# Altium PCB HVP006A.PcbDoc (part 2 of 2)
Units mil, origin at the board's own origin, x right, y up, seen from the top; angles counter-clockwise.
Board outline 1253 x 1919 mil, 4 copper layers (Top Layer, Signal Layer 1, Signal Layer 2, Bottom Layer), stack 61.2 mil thick; 55 components, 14 nets, 102 pads, 51 vias.
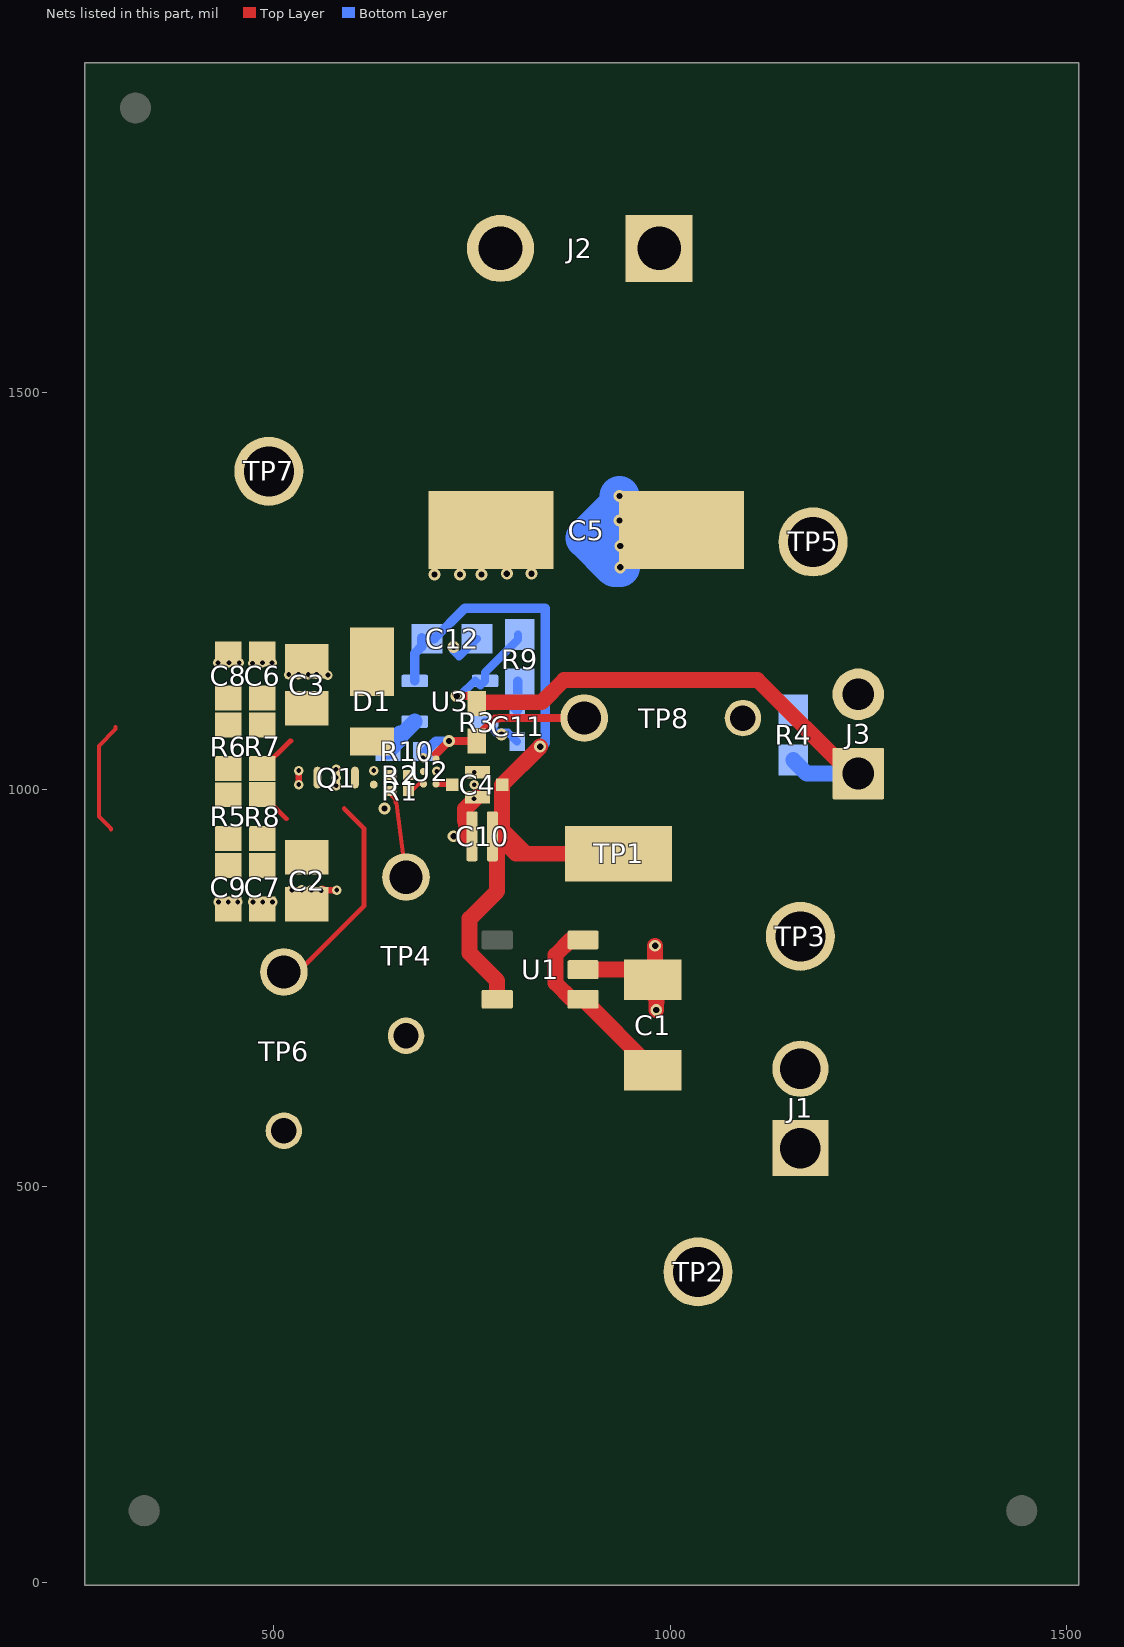
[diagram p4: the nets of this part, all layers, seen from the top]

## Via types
v1: diameter 15, hole 7.87, Top Layer to Bottom Layer, tented both sides, 18 vias
v2: diameter 12, hole 6, Top Layer to Signal Layer 1, tented both sides, 18 vias
v3: diameter 12, hole 6, Top Layer to Bottom Layer, tented both sides, 14 vias
v4: diameter 12, hole 6, Top Layer to Signal Layer 1, tented top, 1 vias

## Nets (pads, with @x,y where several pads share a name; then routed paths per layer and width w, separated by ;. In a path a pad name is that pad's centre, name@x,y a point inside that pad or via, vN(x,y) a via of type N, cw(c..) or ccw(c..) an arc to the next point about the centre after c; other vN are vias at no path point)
5V: C4.1 C10.1 C12.1 TP1.1 U1.5 U3.5 | length 982.2
  Top Layer w20: U1.5@781.87,735.6 781.87,758.87 747.18,793.55 747.18,837.21 781.87,871.9 781.87,939.37 783.5,941 ; C4.1@788,1006 v1(836,1054) ; C4.1@788.5,1006 787.75,1005.25 787.75,949.25 ; TP1.1@935,919 818,919 ; 783.5,941 805.5,919 818,919 ; 783.5,941 786.75,944.25 ; 786.75,944.25 786.75,950.25 787.75,949.25 ; 786.75,944.25 787.75,945.25 787.75,949.25 ; 787.75,949.25 818,919
  Bottom Layer w12: U3.5@677.96,1136.75 677.96,1171.46 686.5,1180 C12.1@686.5,1191 ; C12.1@693.5,1190 702.55,1190 740.75,1228.2 842.4,1228.2 842.4,1058.51 v1@835.73,1051.84
AN: C2.1 C3.1 C5.1 C6.1 C7.1 C8.1 C9.1 D1.1 J2.1 R5.2 R6.2 R7.2 R8.2 TP5.1 | length 314.8
  Top Layer w5: 295,949.39 295,950.8 279.8,966 279.8,1054.8 301,1076 301,1079
  Bottom Layer w50: 933,1317 893,1317 ; v1(936,1370) 936,1360 893,1317 ; v1(937,1280) 930,1280 893,1317
  other v1: 937,1307 936,1339
GATE: Q1.1 R1.2 R2.2 TP4.1 | length 114.1
  Top Layer w5: R1.2@647.98,1000 649.11,998.87 649.11,991.63 653.5,987.23 653.5,983.71 655,982.21 TP4.1@667,889.58
GND: C1.1 C4.3 C10.2 C11.2 C12.2 J1.2 J3.2 Q1.2 R4.1 TP3.1 TP4.2 TP6.2 TP8.2 U1.2 U2.B1 U2.C2 U3.3 | length 331.8
  Top Layer w20: 742.5,941 742.5,959.5 741,961 741,975.25 C4.3@756,990.25 ; U1.2@890.13,773 965.09,773 C1.1@978,760.09 ; v1(981,803) 981,763.09 C1.1@978,760.09 ; v1(982.4,722) 982.4,731.4 983,732 983,737 978,742 C1.1@978,760.09
  Bottom Layer w10: v1(727,1179.8) 727,1174.5 734,1167.5 C12.2@756.5,1190 ; U3.3@766.55,1085.56 780.07,1072.04 791.01,1072.04 795.28,1072.04 C11.2@807,1060.31
  other v1: 727,941 640,976 787.4,1069.4
  other v2: 752.6,988.4 753,1006 753,1021.8 705.8,1023 626.24,1023.86 688.4,1039.8
KA: D1.2 Q1.3 Q1.5 R5.1 R6.1 R7.1 R8.1 TP6.1 | length 362
  Top Layer w6: R8.1@486,993.42 516.21,963.21 ; R7.1@486,1026.25 520.75,1061 522.19,1061 ; TP6.1@513,770 531,770 614,853 614,951 589,976
NetC1_2: C1.2 J1.1 TP2.1 U1.1 U1.3 | length 247.1
  Top Layer w20: U1.3@890.13,810.4 874.4,810.4 855.45,791.45 855.45,756.15 876,735.6 U1.1@890.13,735.6 978,647.73 C1.2@978,645.91
NetC4_2: C4.2 U2.A1 | length 24.4
  Top Layer w8: C4.2@724.5,1007 723.5,1007 U2.A1@708,1007 ; U2.A1@708,1007 U2.A1@704.75,1007 U2.A1@708,1007
  Top Layer w12: C4.2@723.5,1007 C4.2@724.5,1006
NetC11_1: C11.1 R9.2 U3.2 | length 82.4
  Bottom Layer w12: U3.2@766.55,1111.16 795.53,1111.16 C11.1@807,1099.68 808,1100.68 808,1132.5 R9.2@808,1136.44
NetJ3_1: J3.1 R3.2 R4.2 R9.1 U3.1 | length 816.8
  Top Layer w10: v1(730.8,1117.8) R3.2@746.82,1117.8 ; R3.2@757.38,1110 R3.2@756,1111.38 ; R3.2@746.82,1117.8 R3.2@756,1108.62 R3.2@756,1111.38 ; R3.2@746.82,1117.8 754.79,1117.8 756,1116.59 R3.2@756,1111.38
  Top Layer w12: R3.2@756,1108.62 757.38,1110 R3.2@759,1111.62
  Top Layer w20: R3.2@757.38,1110 838,1110 866,1138 1110,1138 1228,1020 J3.1@1237,1020 J3.1@1230,1027
  Bottom Layer w10: v1(730.8,1117.8) 734.48,1117.8 754.08,1137.4 760.64,1130.84 U3.1@766.55,1136.75 766.55,1147.52 808,1188.98 R9.1@808,1195.5
  Bottom Layer w20: R4.2@1155,1037.01 1172.01,1020 J3.1@1237,1020
NetR1_1: R1.1 U2.A2 | length 21.9
  Top Layer w5: R1.1@670.02,1000 676.02,1000 683.02,1007 684.98,1007 U2.A2@689,1007
NetR2_1: R2.1 U2.B2
NetR3_1: R3.1 R10.2 TP8.1 U2.C1 | length 248.2
  Top Layer w8: U2.C1@704.75,1038.5 704.75,1044.75
  Top Layer w10: 704.75,1044.75 v1(721,1061) 755.62,1061 R3.1@756,1061.38 756,1066.8 778.74,1089.54 784.16,1089.54 784.62,1090 TP8.1@890,1090
  Bottom Layer w12: R10.2@691.62,1048 704.62,1061 v1(721,1061)
NetR10_1: R10.1 U3.4 | length 53.5
  Bottom Layer w20: R10.1@644.38,1048 659.36,1062.98 659.36,1070.39 662.79,1070.39 U3.4@677.96,1085.56
PGND: C2.2 C3.2 C5.2 C6.2 C7.2 C8.2 C9.2 J2.2 Q1.4 Q1.6 Q1.7 TP7.1 | length 140.8
  Top Layer w8: C8.2@430.2,1157.82 C8.2@443,1170.61 443,1164 C8.2@444,1163 ; C6.2@474.2,1158.82 C6.2@486,1170.61 C6.2@486,1162.2 ; v2(531.76,1006.14) v2(531.76,1023.86) ; C3.2@541.8,1163.93 C3.2@559.53,1146.2 ; C2.2@542,855.47 561.73,875.2 563.73,873.2 v3(579.8,873.2)
  other v1: 703,1271 735,1271 762,1271 794,1272 825,1272
  other v2: 560,872.4 523.2,873.4 535.6,873.4 547.8,873.4 579,1015 578.8,1025.4 519.2,1144.8 531.4,1144.8 543.6,1144.8 554,1145
  other v3: 430.6,858.2 442.8,858.2 455,858.2 474,858.2 486.4,858.2 498.8,858.2 568.6,1144.2 473.6,1159 430,1159.8 443.8,1159.8 456.8,1159.8 486,1159.8 498.2,1159.8
  other v4: 579,1004.8
pads on no net: FID1.1 FID2.1 FID3.1 H1.0 H2.0 H3.0 H4.0 Q1. U1.4

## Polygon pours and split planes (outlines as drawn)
AN on Top Layer "TOP_LAYER_AN_P036" (solid, remove dead copper, pour order 36): 870,1760 870,1226 1106,1226 1288,1408 1288,1793 1273,1808 1272,1807 891,1807 870,1786
PGND on Top Layer "TOP_LAYER_PGND_P034" (solid, remove dead copper, pour order 34): 303.43,1812.48 299.43,1143 480.3,1143 576.63,1146.51 589,1216 855,1260.62 855,1797 841,1811
AN on Top Layer "TOP_LAYER_AN_P026" (solid, remove dead copper, pour order 26): 295,889 558.12,889 577,907.88 577,955 565,967 434,967 295,967
AN on Top Layer "TOP_LAYER_AN_P010" (solid, remove dead copper, pour order 10): 294,1060.99 516,1066 652,1093 1105,1237 870.31,1263 592,1204 294,1135
KA on Top Layer "TOP_LAYER_KA_P007" (solid, pour order 7): 610.67,1072 296,1047 296,972.63 614,949
5V on Top Layer "TOP_LAYER_5V_P062" (solid, pour order 62): 729,708 844,708 844,1053 841,1050 786,1050 739,1003 729,898
GATE on Top Layer "TOP_LAYER_GATE_P060" (solid, pour order 60): 620,1011 635,1026 641,1026 657,1026 657,992 626,994
NetR1_1 on Top Layer "TOP_LAYER_NETR1_1_P006" (solid, pour order 6): 663,1005 663,993 687,993 694,1000 694,1003 694,1013 669,1013 663,1007
NetR2_1 on Top Layer "TOP_LAYER_NETR2_1_P056" (solid, pour order 56): 661,1028 661,1011 672,1011 678,1017 688,1017 695,1017 696,1018 696,1028
PGND on Top Layer "TOP_LAYER_PGND_P016" (solid, remove dead copper, pour order 16): 416.44,940.13 417.44,939.13 417.44,874 291,874 291,72 688,72 688,759.57 554.44,893.13 547.44,893.13 457.44,890.13 449.44,910.13
NetC1_2 on Top Layer "TOP_LAYER_NETC1_2_P038" (solid, remove dead copper, pour order 38): 709,665 710,664 710,58 1276,58 1276,342 1276,597 1272,601 1080,601 1000,681 996,681 924,834.02 851.75,834.02 837,736
GND on Top Layer "TOP_LAYER_GND_P040" (solid, remove dead copper, pour order 40): 941,808 939,806 939,723 1052,610 1250,610 1267,627 1267,647 1269,649 1269,850 1223,896 1151,896 1088,896 1019,827
PGND on Signal Layer 1 "SIGNAL_LAYER_1_PGND_P008" (solid, remove dead copper, pour order 8): 319,72 1280,72 1280,1889.01 319,1889
GND on Signal Layer 1 "SIGNAL_LAYER_1_GND_P005" (solid, remove dead copper, pour order 5): 620,1035 620,1003.51 667,940 667,852 476,852 476,53 1287.31,53 1287.31,1228 659,1228 659,1035
GND on Signal Layer 2 "SIGNAL_LAYER_2_GND_P046" (solid, remove dead copper, pour order 46): 620,1034 620,1003.51 667,940 667,852 476,852 476,53 1287.31,53 1287.31,1228 665.37,1228 665.37,1034
PGND on Signal Layer 2 "SIGNAL_LAYER_2_PGND_P048" (solid, pour order 48): 305,80 1273.51,80 1283.5,1868 305,1868
PGND on Bottom Layer "BOTTOM_LAYER_PGND_P052" (solid, pour order 52): 307,741 307,68 462,68 1277.39,1095 1277.39,1862 307,1862
GND on Bottom Layer "BOTTOM_LAYER_GND_P004" (solid, remove dead copper, pour order 4): 628,992.7 667,940 667,852 476,852 476,53 1287.31,53 1287.31,1233 628,1233

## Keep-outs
Keep-Out Layer:
  text ".Layer_Name" at 577,-858.49 h60

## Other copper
Top Layer:
  rectangle net GND: 628,964 646,984.13
  rectangle net KA: 576.4,965.87 598,986
  text ".Layer_Name" at 577,-858.49 h60
Bottom Layer:
  text ".Layer_Name" at 577,-858.49 h60

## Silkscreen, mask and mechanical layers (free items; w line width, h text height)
Top Overlay:
  lines w3.94: 570.52,1088.71 571.76,1087.47 571.76,1043.24 571.76,1040.81 578.58,1034 657,1034 669,1046 669,1061 ; 571.88,977 792,977 803,988 803,988.99 803,1052 794,1061 669,1061 ; 667,1059 669,1061
  lines w10: 357,1330 357,1248 419,1186 ; 418,834 419,835 ; 420,1185 419,1186 ; 569,1090.73 569,1185 419,1186 ; 570.88,978 570,835 568,833 567,833 565,835 419,835 ; 419,835 419,1186
  text "Driver and Load / Area: 42sqmm" at 474,1326 h72.83 r90
  text ".Layer_Name" at 577,-858.49 h60
Bottom Overlay:
  text ".Layer_Name" at 577,-858.49 h60
Top Paste:
  text ".Layer_Name" at 577,-858.49 h60
Bottom Paste:
  text ".Layer_Name" at 577,-858.49 h60
Top Solder:
  circle w10: c587,976 r4.24
  circle w10: c638,974 r3.61
  rectangle: 300,895 417,953
  rectangle: 301,981 418,1039
  rectangle: 302,1067 419,1125
  text ".Layer_Name" at 577,-858.49 h60
  text ".Layer_Name" at 577,-858.49 h60
Bottom Solder:
  text ".Layer_Name" at 577,-858.49 h60
Drill Guide:
  text ".Layer_Name" at 577,-858.49 h60
M1 Board Outline:
  lines w10: 258,-2 258,1911 263,1916 1516,1916 1517,1915 1517,3 1512,-2 258,-2
  text ".Layer_Name" at 577,-858.49 h60
M2 Board Dimensions:
  text ".Layer_Name" at 577,-858.49 h60
M3 3D STEP Top:
  text ".Layer_Name" at 577,-858.49 h60
M4 3D STEP Bottom:
  text ".Layer_Name" at 577,-858.49 h60
M5 Assembly Top:
  lines w10: -292,-930.17 6308,-930.17 ; -292,-726.83 6310,-726.83 ; -292,-523.5 -292,-1133.5 3713,-1133.5 6310,-1133.5 6310,-523.5 -291.5,-523.5 -291.5,-1133.5 1284,-1133.5 ; 2173,-1133.5 2173,-523.5 ; 3440,-726.83 3440,-523.5 ; 4280,-726.83 4280,-523.5 ; 4902,-1140 4902,-937.17
  text "COMPONENTS MARKED 'DNP' SHOULD NOT BE POPULATED." at 1153.5,-318.5 h60
  text "ASSEMBLY VARIANT:" at 1153,-434 h60
  text ".VariantName" at 2189,-434 h60
  text "PCB VIEWED FROM TOP SIDE" at -228.5,-655.67 h60
  text "BOARD #:" at 2248,-655.67 h60
  text ".PRJ_Number" at 2793.5,-655.67 h60
  text "REV:" at 3638,-655.67 h60
  text ".PCB_Rev" at 3929.5,-655.67 h60
  text "SVN REV:" at 4476,-655.67 h60
  text ".VersionControl_RevNumber" at 4982,-655.67 h60
  text "TID #:" at 2248,-859 h60
  text ".TID" at 2793.5,-859 h60
  text "PLOT NAME =" at -228.5,-1064.34 h60
  text ".plot_File_Name" at 577,-1064.34 h60
  text "GENERATED    :" at 2250,-1064.34 h60
  text ".Print_Date" at 3119.5,-1064.34 h60
  text ".Print_Time" at 3848.5,-1064.34 h60
  text "TEXAS INSTRUMENTS" at 5113,-1064.34 h60
M6 Assembly Bottom:
  lines w10: -292.5,-727.33 6309.5,-727.33 ; -290.5,-930.67 6309.5,-930.67 ; 1115.5,-1140.5 1115.5,-937.67 ; 1737.5,-727.33 1737.5,-524 ; 2577.5,-727.33 2577.5,-524 ; 3844.5,-1134 3844.5,-524 ; 4733.5,-1134 6309,-1134 6309,-524 -292.5,-524 -292.5,-1134 2304.5,-1134 6309.5,-1134 6309.5,-524
  text "COMPONENTS MARKED 'DNP' SHOULD NOT BE POPULATED." at 6102,-318 h60
  text ".VariantName" at 5058,-434 h60
  text "ASSEMBLY VARIANT:" at 6097,-434 h60
  text ".VersionControl_RevNumber" at 1035.5,-656.17 h60
  text "SVN REV:" at 1541.5,-656.17 h60
  text ".PCB_Rev" at 2088,-656.17 h60
  text "REV:" at 2379.5,-656.17 h60
  text ".PRJ_Number" at 3224,-656.17 h60
  text "BOARD #:" at 3769.5,-656.17 h60
  text "PCB VIEWED FROM BOTTOM SIDE" at 6246,-656.17 h60
  text ".TID" at 3224,-859.5 h60
  text "TID #:" at 3769.5,-859.5 h60
  text "TEXAS INSTRUMENTS" at 904.5,-1064.84 h60
  text ".Print_Time" at 2169,-1064.84 h60
  text ".Print_Date" at 2898,-1064.84 h60
  text "GENERATED    :" at 3767.5,-1064.84 h60
  text ".plot_File_Name" at 5440.5,-1064.84 h60
  text "PLOT NAME =" at 6246,-1064.84 h60
M9 Title Sheet:
  drawing of 57 lines, arcs and shapes, not listed
  text "1" at 739.84,8036.5 h70
  text "2" at 3235.5,8036.5 h70
  text "3" at 5724.84,8036.5 h70
  text "4" at 8231.51,8036.5 h70
  text "5" at 10730.5,8036.5 h70
  text "6" at 13235.5,8036.5 h70
  text "A" at -416.5,6893.5 h70
  text "A" at 14383.5,6893.5 h70
  text "B" at -416.5,4513.5 h70
  text "B" at 14383.5,4513.5 h70
  text "C" at -416.5,2138.5 h70
  text "C" at 14383.5,2138.5 h70
  text "PROJECT TITLE:" at 11343.5,277.5 h45
  text ".PRJ_Title" at 11393.5,144.17 h70
  text "DESIGNED FOR:" at 11343.5,-23.5 h45
  text ".PRJ_Customer" at 11393.5,-163.5 h70
  text "D" at -416.5,-231.5 h70
  text "D" at 14383.5,-231.5 h70
  text "FILE NAME:" at 11343.5,-323.5 h45
  text ".PCB_File_Name_No_Path" at 11393.5,-443.5 h70
  text "Texas Instruments (TI) and/or its licensors do not warrant the accuracy or completeness of this specification" at 6374,-605.34 h45
  text "ENGINEER:" at 11343.5,-613.5 h45
  text "LAYOUT BY:" at 12848.5,-613.5 h45
  text "or any information contained therein. TI and/or its licensors do not warrant that this design will meet" at 6329.01,-718 h45
  text ".PRJ_Engineer" at 11393.5,-768.49 h70
  text ".PCB_Layout" at 12899,-768.49 h70
  text "the specifications, will be suitable for your application or fit for any particular purpose, or will operate in" at 6329.01,-830.67 h45
  text ".Layer_Name" at 577,-858.49 h60
  text "ALTIUM DESIGNER VERSION:" at 12848.5,-923.5 h45
  text "an implementation. TI and/or its licensors do not warrant that the design is production worthy. You should" at 6329.01,-943.33 h45
  text "completely validate and test your design implementation to confirm the system functionality for your application." at 6374,-1056 h45
  text ".print_Scale" at 11393.5,-1056.83 h70
  text ".Application_BuildNumber" at 12899,-1056.83 h70
  text "1" at 739.84,-1263.5 h70
  text "2" at 3235.5,-1263.5 h70
  text "3" at 5724.84,-1263.5 h70
  text "4" at 8231.51,-1263.5 h70
  text "5" at 10730.5,-1263.5 h70
  text "6" at 13235.5,-1263.5 h70
M10 Fab Notes:
  drawing of 173 lines, arcs and shapes, not listed
  text "DESIGN INFORMATION" at 12378.02,6201 h60
  text "MIN. TRACK WIDTH:" at 11733.46,6021 h60
  text "5" at 12829.7,6021 h60
  text "MIL" at 12984.46,6021 h60
  text "MIN. CLEARANCE:" at 11733.46,5889 h60
  text "0.2" at 12769.7,5889 h60
  text "mm" at 12984.46,5889 h60
  text "MIN. VIA PAD SIZE:" at 11733.46,5757 h60
  text "10" at 12799.71,5757 h60
  text "MIL" at 12984.46,5757 h60
  text "0.05mm (2MIL)" at 12428.46,5615.29 h60
  text "MINIMUM ANNULAR RING" at 11404.23,5611 h60
  text "EXTERNAL" at 13136.46,5611 h60
  text "PER" at 11604.23,5493 h60
  text "IPC-D-275 CLASS 2 LEVEL C" at 11824.23,5493 h60
  text "MIL, HOLES" at 13312.46,5380.71 h60
  text "+/-" at 12920,5380 h60
  text "+/-" at 13774,5380 h60
  text "REGISTRATION TOLERANCES:" at 11404.23,5375 h60
  text "METAL" at 12604,5375 h60
  text "5" at 13180.2,5375 h60
  text "3" at 14013.2,5375 h60
  text "MIL" at 14129.46,5375 h60
  text "+/-" at 13774,5262 h60
  text "HOLE SIZE TOLERANCE (UNLESS OTHERWISE SPECIFIED):" at 11404.23,5257 h60
  text "3" at 14013.2,5257 h60
  text "MIL" at 14129.46,5257 h60
  text "NOTE:  Fill all 6 mil vias and plate shut then polish flat." at 11393.8,5097 h90
  text "MATERIAL:" at 11329.46,5047.54 h60
  text "FR-4 High Tg" at 12315.9,4907.21 h60
  text "FR-408" at 11750.46,4898.64 h60
  text "OTHER" at 13238.46,4898.64 h60
  text "X" at 12161,4895 h60
  text "62 MIL (1.6mm) +/-10%" at 12070.56,4735.92 h60
  text "THICKNESS:" at 11404.23,4731.64 h60
  text "X" at 11942.4,4731.64 h60
  text "OTHER" at 13355.46,4731.64 h60
  text "TOLERANCE:" at 11404.23,4573.64 h60
  text "X" at 12243.53,4573.64 h60
  text "ANSI IPC-6012 TYPE 3 CLASS 2" at 12430.48,4573.64 h60
  text "OTHER +/-" at 12430.46,4417.64 h60
  text "BOW & TWIST:" at 11404.23,4260.64 h60
  text "X" at 12243.53,4260.64 h60
  text "ANSI IPC-6012 TYPE 3 CLASS 2" at 12430.48,4260.64 h60
  text "OTHER +/-" at 12430.46,4102.13 h60
  text "DRILLING:" at 11329.46,3963.64 h60
  text "REFERENCE:" at 11404.23,3846.64 h60
  text "X" at 12052.46,3846.64 h60
  text "AS SHOWN" at 12239.46,3846.64 h60
  text "X" at 12953.46,3846.64 h60
  text "NC_DRILL FILES" at 13090.46,3846.64 h60
  text "PTH COPPER THICKNESS:" at 11404.23,3688.64 h60
  text "X" at 12534.46,3688.64 h60
  text "20-30 um" at 12671.46,3688.64 h60
  text "OTHER" at 13388.46,3688.64 h60
  text "BOARD FINISH:" at 11329.46,3529.64 h60
  text "SILKSCREEN:" at 11484.68,3411.64 h60
  text "X" at 12433.46,3411.64 h60
  text "TOP" at 12559.46,3411.64 h60
  text "X" at 12943.46,3411.64 h60
  text "BOTTOM" at 13070.46,3411.64 h60
  text "FAB NOTE:  Fill all 6 mil vias and plate shut then polish flat." at 26.4,3323.6 h90
  text "SILKSCREEN COLOR:" at 11484.68,3244.64 h60
  text "X" at 12432.42,3244.64 h60
  text "WHITE" at 12559.46,3244.64 h60
  text "OTHER" at 13070.46,3244.64 h60
  text "X" at 12563.42,3085.44 h60
  text "GREEN" at 12690.46,3085.44 h60
  text "OTHER" at 13308.46,3085.44 h60
  text "SOLDER RESIST COLOR:" at 11484.68,3074.64 h60
  text "X" at 12563.42,2915.44 h60
  text "MATTE" at 12690.46,2915.44 h60
  text "SEMI-GLOSS" at 13308,2914.8 h60
  text "IMMERSION GOLD (ENIG)" at 12390.46,2726.92 h60
  text "ENEPIG" at 13728,2723.64 h60
  text "SURFACE FINISH:" at 11329.46,2722.64 h60
  text "X" at 12203.51,2722.64 h60
  text "IMM. TIN/SILVER OR EQUIV" at 11659,2565.64 h60
  text "OTHER" at 13090.46,2565.64 h60
  text "ARRAY/PANEL:" at 11329.46,2386.64 h60
  text "CUT AND TRIM PER M1 BOARD OUTLINE" at 12390.46,2382.35 h60
  text "N.C. ROUTE" at 12390.46,2230.64 h60
  text "X" at 13069.46,2230.64 h60
  text "V. SCORE" at 13256.46,2230.64 h60
  text "CERTIFICATION:" at 11329.46,2093.64 h60
  text "MATERIALS AND WORKMANSHIP FOR ALL PCBS" at 12054.46,2093.64 h60
  text "TO MEET OR EXCEED THE REQUIREMENTS OF:" at 12054.46,1995.64 h60
  text "X" at 11680.96,1859.13 h60
  text "ANSI IPC-A-600F CLASS ->" at 11819.96,1859.13 h60
  text "X" at 13459.02,1859.13 h60
  text "2" at 13577.96,1859.14 h60
  text "1" at 13262.96,1857.64 h60
  text "3" at 13931.96,1857.64 h60
  text "X" at 12495.02,1699.64 h60
  text "RoHS" at 12631.96,1699.64 h60
  text "OTHER" at 13276.36,1699.64 h60
  text "PER ORDER" at 13673.42,1699.64 h60
  text "ALL BOARDS MUST MEET OR EXCEED UL94-V0 REQUIREMENTS." at 11357,1534 h60
  text "PCB MUST BEAR THE UL94V-0 UL REGISTERED MATERIAL ID NUMBER" at 11357,1414 h60
  text "ADDITIONAL REQUIREMENTS:" at 11329.46,1240.64 h60
  text "MICROSECTION:" at 11404.23,1125.64 h60
  text "YES" at 12309.96,1125.64 h60
  text "REQUIRED" at 13171.46,969.49 h60
  text "BARE BOARD ELEC. TEST:" at 11404.23,966.64 h60
  text "NONE" at 12709.96,966.64 h60
  text "X" at 13044.46,966.64 h60
  text "PER ORDER" at 13763.46,966.64 h60
  text ".Layer_Name" at 577,-858.49 h60
M11 Gerber Information:
  lines w10: -292,-930.17 6308,-930.17 ; -292,-726.83 6310,-726.83 ; -292,-523.5 -292,-1133.5 3713,-1133.5 6310,-1133.5 6310,-523.5 -291.5,-523.5 -291.5,-1133.5 1284,-1133.5 ; 2173,-1133.5 2173,-523.5 ; 3440,-726.83 3440,-523.5 ; 4280,-726.83 4280,-523.5 ; 4902,-1140 4902,-937.17
  text "ALL ARTWORK VIEWED FROM TOP SIDE" at -228.5,-655.67 h60
  text "BOARD #:" at 2248,-655.67 h60
  text ".PRJ_Number" at 2793.5,-655.67 h60
  text "REV:" at 3638,-655.67 h60
  text ".PCB_Rev" at 3929.5,-655.67 h60
  text "SVN REV:" at 4476,-655.67 h60
  text ".VersionControl_RevNumber" at 4982,-655.67 h60
  text "LAYER NAME =" at -228.5,-858.49 h60
  text "TID #:" at 2248,-859 h60
  text ".TID" at 2793.5,-859 h60
  text "PLOT NAME =" at -228.5,-1064.34 h60
  text ".plot_File_Name" at 577,-1064.34 h60
  text "GENERATED    :" at 2250,-1064.34 h60
  text ".Print_Date" at 3119.5,-1064.34 h60
  text ".Print_Time" at 3848.5,-1064.34 h60
  text "TEXAS INSTRUMENTS" at 5113,-1064.34 h60
M12 Stackup:
  drawing of 295 lines, arcs and shapes, not listed
  text "Layer" at 9728.74,7834 h60
  text "Name" at 10138.66,7834 h60
  text "Material" at 11078.4,7834 h60
  text "Thickness" at 11938.16,7834 h60
  text "Constant" at 12588,7834 h60
  text "Board Layer Stack" at 13157.86,7834 h60
  text "1" at 9728.74,7714 h60
  text "Top Overlay" at 10138.66,7714 h60
  text "2" at 9728.74,7594 h60
  text "Top Solder" at 10138.66,7594 h60
  text "Solder Resist" at 11078.4,7594 h60
  text "0.40mil" at 11938.16,7594 h60
  text "3.5" at 12588,7594 h60
  text "3" at 9728.74,7474 h60
  text "Top Layer" at 10138.66,7474 h60
  text "Copper" at 11078.4,7474 h60
  text "1.40mil" at 11938.16,7474 h60
  text "4" at 9728.74,7354 h60
  text "Dielectric1" at 10138.66,7354 h60
  text "FR-4" at 11078.4,7354 h60
  text "5.00mil" at 11938.16,7354 h60
  text "4.2" at 12588,7354 h60
  text "5" at 9728.74,7234 h60
  text "Signal Layer 1" at 10138.66,7234 h60
  text "Copper" at 11078.4,7234 h60
  text "1.42mil" at 11938.16,7234 h60
  text "6" at 9728.74,7114 h60
  text "Dielectric 3" at 10138.66,7114 h60
  text "45.57mil" at 11938.16,7114 h60
  text "4.2" at 12588,7114 h60
  text "7" at 9728.74,6994 h60
  text "Signal Layer 2" at 10138.66,6994 h60
  text "Copper" at 11078.4,6994 h60
  text "1.42mil" at 11938.16,6994 h60
  text "8" at 9728.74,6874 h60
  text "Dielectric 2" at 10138.66,6874 h60
  text "5.00mil" at 11938.16,6874 h60
  text "4.2" at 12588,6874 h60
  text "9" at 9728.74,6754 h60
  text "Bottom Layer" at 10138.66,6754 h60
  text "Copper" at 11078.4,6754 h60
  text "1.40mil" at 11938.16,6754 h60
  text "10" at 9728.74,6634 h60
  text "Bottom Solder" at 10138.66,6634 h60
  text "Solder Resist" at 11078.4,6634 h60
  text "0.40mil" at 11938.16,6634 h60
  text "3.5" at 12588,6634 h60
  text "11" at 9728.74,6514 h60
  text "Bottom Overlay" at 10138.66,6514 h60
  text ".Layer_Name" at 577,-858.49 h60
M13 Component Bodies Top:
  text ".Layer_Name" at 577,-858.49 h60
M14 Component Bodies Bottom:
  text ".Layer_Name" at 577,-858.49 h60
M15 Courtyards Top:
  text ".Layer_Name" at 577,-858.49 h60
M16 Courtyards Bottom:
  text ".Layer_Name" at 577,-858.49 h60
Drill Drawing:
  circle w10: c5936.73,2870.26 r27.63
  lines w10: 5909.1,2345.28 5964.36,2345.28 5964.36,2400.54 5909.1,2400.54 5909.1,2345.28 ; 5909.1,2524.88 5964.36,2524.88 5936.73,2469.62 5909.1,2524.88 ; 5909.1,2607.77 5922.91,2607.77 5936.73,2593.95 5950.54,2607.77 5964.36,2607.77 5950.54,2621.58 5964.36,2635.4 5950.54,2635.4 5936.73,2649.22 5922.91,2635.4 5909.1,2635.4 5922.91,2621.58 5909.1,2607.77 ; 5909.1,2718.29 5936.73,2732.1 5964.36,2718.29 5950.54,2745.92 5964.36,2773.55 5936.73,2759.73 5909.1,2773.55 5922.91,2745.92 5909.1,2718.29 ; 5909.1,2966.96 5964.36,2966.96 5964.36,3022.22 5909.1,3022.22 5909.1,2966.96 ; 5909.1,3091.3 5909.1,3105.11 5922.91,3118.93 5909.1,3132.74 5909.1,3146.56 5922.91,3146.56 5936.73,3132.74 5950.54,3146.56 5964.36,3146.56 5964.36,3132.74 5950.54,3118.93 5964.36,3105.11 5964.36,3091.3 5950.54,3091.3 5936.73,3105.11 5922.91,3091.3 5909.1,3091.3 ; 5909.1,3243.26 5936.73,3215.63 5964.36,3243.26 5936.73,3270.89 5909.1,3243.26 ; 5920.15,2978.01 5953.3,2978.01 5953.3,3011.17 5920.15,3011.17 5920.15,2978.01
  lines w12: 5806.2,1755.33 9044.82,1755.33 ; 5806.2,1879.66 9044.82,1879.66 ; 5859,2307.98 8934.93,2307.98 ; 5859,3302.66 8934.93,3302.66 ; 6143.95,1630.99 6143.95,2004 ; 6196.75,2183.65 6196.75,3427 ; 6475.76,1630.99 6475.76,2004 ; 6528.56,2183.65 6528.56,3427 ; 7111.86,1630.99 7111.86,2004 ; 7164.66,2183.65 7164.66,3427 ; 7370.86,1630.99 7370.86,2004 ; 7423.66,2183.65 7423.66,3427 ; 7745.84,1630.99 7745.84,2004 ; 7798.64,2183.65 7798.64,3427 ; 8478.63,1630.99 8478.63,2004 ; 8522.86,2183.65 8522.86,3427 ; 5806.2,1630.99 9044.82,1630.99 9044.82,2004 5806.2,2004 5806.2,1630.99 ; 5859,2183.65 8934.93,2183.65 8934.93,3427 5859,3427 5859,2183.65
  text "Symbol" at 5933.6,3339.97 h72
  text "Quantity" at 6234.05,3339.97 h72
  text "Finished Hole Size" at 6565.86,3339.97 h72
  text "Plated" at 7201.96,3339.97 h72
  text "Hole Type" at 7460.96,3339.97 h72
  text "Drill Layer Pair" at 7835.94,3339.97 h72
  text "Tolerance" at 8560.16,3339.97 h72
  text "14" at 6234.05,3215.63 h60
  text "6.00mil (0.152mm)" at 6565.86,3215.63 h60
  text "PTH" at 7201.96,3215.63 h60
  text "Round" at 7460.96,3215.63 h60
  text "Top Layer - Bottom Layer" at 7835.94,3215.63 h60
  text "18" at 6234.05,3091.3 h60
  text "7.87mil (0.200mm)" at 6565.86,3091.3 h60
  text "PTH" at 7201.96,3091.3 h60
  text "Round" at 7460.96,3091.3 h60
  text "Top Layer - Bottom Layer" at 7835.94,3091.3 h60
  text "3" at 6234.05,2966.96 h60
  text "32.00mil (0.813mm)" at 6565.86,2966.96 h60
  text "PTH" at 7201.96,2966.96 h60
  text "Round" at 7460.96,2966.96 h60
  text "Top Layer - Bottom Layer" at 7835.94,2966.96 h60
  text "2" at 6234.05,2842.62 h60
  text "40.00mil (1.016mm)" at 6565.86,2842.62 h60
  text "PTH" at 7201.96,2842.62 h60
  text "Round" at 7460.96,2842.62 h60
  text "Top Layer - Bottom Layer" at 7835.94,2842.62 h60
  text "3" at 6234.05,2718.29 h60
  text "42.00mil (1.067mm)" at 6565.86,2718.29 h60
  text "PTH" at 7201.96,2718.29 h60
  text "Round" at 7460.96,2718.29 h60
  text "Top Layer - Bottom Layer" at 7835.94,2718.29 h60
  text "2" at 6234.05,2593.95 h60
  text "51.18mil (1.300mm)" at 6565.86,2593.95 h60
  text "PTH" at 7201.96,2593.95 h60
  text "Round" at 7460.96,2593.95 h60
  text "Top Layer - Bottom Layer" at 7835.94,2593.95 h60
  text "2" at 6234.05,2469.62 h60
  text "55.12mil (1.400mm)" at 6565.86,2469.62 h60
  text "PTH" at 7201.96,2469.62 h60
  text "Round" at 7460.96,2469.62 h60
  text "Top Layer - Bottom Layer" at 7835.94,2469.62 h60
  text "4" at 6234.05,2345.28 h60
  text "63.00mil (1.600mm)" at 6565.86,2345.28 h60
  text "PTH" at 7201.96,2345.28 h60
  text "Round" at 7460.96,2345.28 h60
  text "Top Layer - Bottom Layer" at 7835.94,2345.28 h60
  text "48 Total" at 6234.05,2220.95 h60
  text "Symbol" at 5880.8,1916.97 h72
  text "Quantity" at 6181.25,1916.97 h72
  text "Finished Hole Size" at 6513.06,1916.97 h72
  text "Plated" at 7149.16,1916.97 h72
  text "Hole Type" at 7408.16,1916.97 h72
  text "Drill Layer Pair" at 7783.14,1916.97 h72
  text "Hole Tolerance" at 8515.93,1916.97 h72
  text "19" at 6181.25,1792.63 h60
  text "6.00mil (0.152mm)" at 6513.06,1792.63 h60
  text "PTH" at 7149.16,1792.63 h60
  text "Round" at 7408.16,1792.63 h60
  text "Top Layer - Signal Layer 1" at 7783.14,1792.63 h60
  text "A" at 5855.51,1782.64 h55.26
  text "19 Total" at 6181.25,1668.3 h60
  text ".Layer_Name" at 577,-858.49 h60
M17 Embedded Cavity:
  text ".Layer_Name" at 577,-858.49 h60
M18 Embedded Assembly:
  text ".Layer_Name" at 577,-858.49 h60
M19 Embedded Keepout:
  text ".Layer_Name" at 577,-858.49 h60

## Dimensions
253.4,-10.2 to 1523,-13.2 on M2 Board Dimensions
251.6,1922 to 253.4,-10.2 on M2 Board Dimensions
